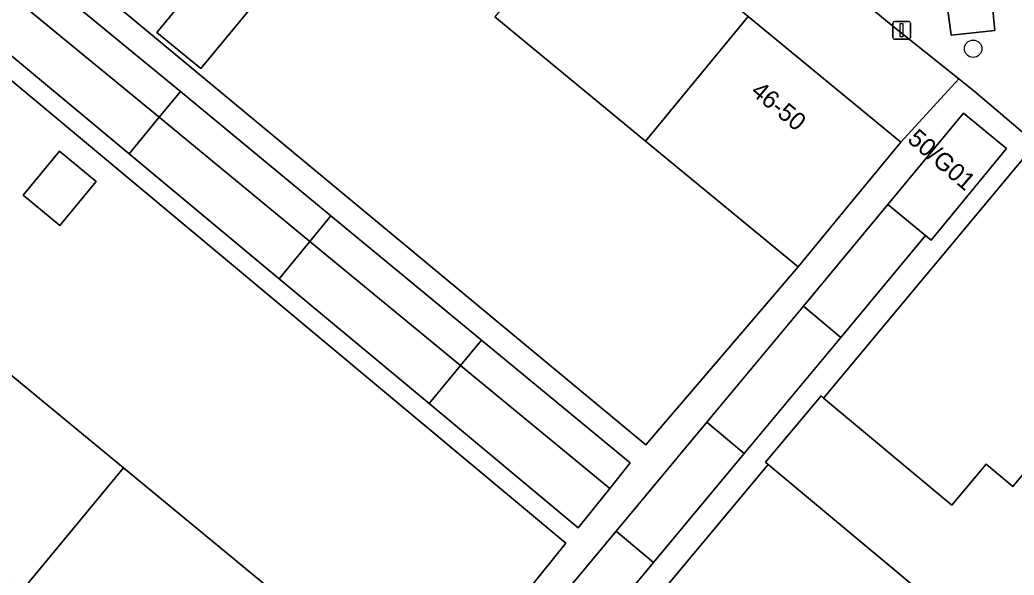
# Model space of a CAD drawing. Extents: x 162073 to 163043, y 381818 to 382561.
# Drawn here: x 162389.4 to 162445.3, y 382038.3 to 382069.6 of the extents above; entities that cross this region are included whole.
import ezdxf

# ---------------------------------------------------------------- set-up
doc = ezdxf.new("R2010")
doc.units = 0
for name, color, linetype in [('IMGEO_Boom', 7, 'Continuous'), ('IMGEO_Erf', 7, 'Continuous'), ('IMGEO_Lichtmast', 7, 'Continuous'), ('IMGEO_Pand', 7, 'Continuous'), ('IMGEO_Pand_nummerreeks', 7, 'Continuous'), ('IMGEO_Parkeervlak_open', 7, 'Continuous'), ('IMGEO_Voetpad_open', 7, 'Continuous')]:
    doc.layers.add(name, color=color, linetype=linetype)

msp = doc.modelspace()

# ---------------------------------------------------------------- linework, layer by layer
at = {"layer": 'IMGEO_Boom'}
msp.add_circle((162443, 382067.946), 0.489, dxfattribs=at)
at = {"layer": 'IMGEO_Erf'}
for points in [[(162374.058, 382122.534), (162370.927, 382118.714), (162379.513, 382111.639), (162387.985, 382104.658), (162396.457, 382097.677), (162404.928, 382090.697), (162413.399, 382083.717), (162421.871, 382076.736), (162430.342, 382069.755), (162438.929, 382062.68), (162442.197, 382066.248), (162438.394, 382069.293)], [(162352.681, 382096.404), (162344.316, 382086.382), (162352.799, 382079.379), (162361.282, 382072.376), (162369.765, 382065.374), (162378.248, 382058.371), (162386.731, 382051.368), (162395.214, 382044.365), (162403.697, 382037.363), (162412.215, 382030.331), (162420.1, 382040.13)], [(162393.681, 382060.479), (162391.639, 382058.007), (162389.571, 382059.714), (162391.612, 382062.187)]]:
    msp.add_lwpolyline(points, close=True, dxfattribs=at)
for points in [[(162367.87, 382092.748), (162424.591, 382045.656), (162433.159, 382055.677), (162424.572, 382062.752), (162416.1, 382069.733)], [(162406.221, 382074.898), (162399.57, 382066.827), (162397.097, 382068.865), (162398.824, 382070.962)], [(162454.536, 382056.174), (162446.525, 382062.616), (162434.583, 382048.291), (162441.797, 382042.258), (162443.737, 382044.571), (162445.238, 382043.312), (162447.3, 382045.77), (162449.243, 382048.087), (162447.533, 382049.521), (162450.592, 382053.167), (162452.277, 382051.753), (162454.432, 382054.322)], [(162430.078, 382030.919), (162432.415, 382033.705), (162433.745, 382032.589), (162436.679, 382036.087), (162438.155, 382034.848), (162440.187, 382037.271), (162431.473, 382044.558), (162411.121, 382020.146)]]:
    msp.add_lwpolyline(points, dxfattribs=at)
at = {"layer": 'IMGEO_Lichtmast'}
for p, q in [((162438.48, 382068.581), (162438.48, 382069.381)), ((162438.48, 382069.381), (162438.48, 382068.581)), ((162438.58, 382069.481), (162439.37, 382069.481)), ((162439.37, 382069.481), (162438.58, 382069.481)), ((162439.47, 382069.381), (162439.47, 382068.581)), ((162439.47, 382068.581), (162439.47, 382069.381)), ((162439.37, 382068.481), (162438.58, 382068.481)), ((162438.58, 382068.481), (162439.37, 382068.481))]:
    msp.add_line(p, q, dxfattribs=at)
msp.add_lwpolyline([(162438.9, 382069.356), (162439.05, 382069.356), (162439.05, 382068.606), (162438.9, 382068.606), (162438.9, 382069.356)], dxfattribs=at)
for centre, start, end in [((162438.58, 382069.381), 90, 180), ((162438.58, 382069.381), 90, 180), ((162439.37, 382069.381), 0, 90), ((162439.37, 382069.381), 360, 90), ((162438.58, 382068.581), 180, 270), ((162438.58, 382068.581), 180, 270), ((162439.37, 382068.581), 270, 0), ((162439.37, 382068.581), 270, 0)]:
    msp.add_arc(centre, 0.1, start, end, dxfattribs=at)
at = {"layer": 'IMGEO_Pand'}
for points in [[(162404.928, 382090.697), (162399.157, 382083.694), (162397.197, 382081.316), (162401.766, 382077.552), (162397.342, 382072.183), (162398.824, 382070.962), (162397.097, 382068.865), (162399.57, 382066.827), (162406.221, 382074.898), (162405.257, 382075.693), (162406.717, 382077.465), (162407.629, 382076.713), (162413.399, 382083.717)], [(162424.572, 382062.752), (162430.342, 382069.755), (162421.871, 382076.736), (162416.1, 382069.733)], [(162389.955, 382072.525), (162388.753, 382071.067), (162397.225, 382064.085), (162398.418, 382065.534)], [(162395.528, 382062.026), (162397.225, 382064.085), (162388.753, 382071.067), (162387.093, 382069.052)], [(162424.572, 382062.752), (162433.159, 382055.677), (162435.75, 382058.822), (162438.929, 382062.68), (162430.342, 382069.755)], [(162397.225, 382064.085), (162405.695, 382057.105), (162406.881, 382058.544), (162398.418, 382065.534)], [(162444.879, 382062.326), (162442.45, 382064.327), (162438.206, 382059.176), (162440.325, 382057.43), (162440.635, 382057.175)], [(162395.528, 382062.026), (162403.962, 382055.001), (162405.695, 382057.105), (162397.225, 382064.085)], [(162393.681, 382060.479), (162391.612, 382062.187), (162389.571, 382059.714), (162391.639, 382058.007)], [(162440.325, 382057.43), (162438.206, 382059.176), (162433.451, 382053.462), (162435.561, 382051.705)], [(162406.881, 382058.544), (162405.695, 382057.105), (162414.167, 382050.123), (162415.345, 382051.553)], [(162412.397, 382047.975), (162414.167, 382050.123), (162405.695, 382057.105), (162403.962, 382055.001)], [(162433.451, 382053.462), (162428.013, 382046.927), (162430.124, 382045.17), (162435.561, 382051.705)], [(162381.001, 382044.426), (162389.484, 382037.423), (162395.214, 382044.365), (162386.731, 382051.368)], [(162414.167, 382050.123), (162422.567, 382043.201), (162423.719, 382044.636), (162415.345, 382051.553)], [(162412.397, 382047.975), (162420.788, 382040.985), (162422.567, 382043.201), (162414.167, 382050.123)], [(162447.3, 382045.77), (162445.238, 382043.312), (162443.737, 382044.571), (162441.797, 382042.258), (162434.583, 382048.291), (162434.446, 382048.406), (162431.329, 382044.679), (162431.473, 382044.558), (162440.187, 382037.271), (162446.937, 382031.626), (162447.733, 382032.574), (162448.308, 382032.092), (162449.816, 382033.89), (162449.21, 382034.398), (162451.7, 382037.366), (162452.284, 382036.876), (162453.838, 382038.728), (162453.287, 382039.19), (162454.063, 382040.114)], [(162430.124, 382045.17), (162428.013, 382046.927), (162422.917, 382040.802), (162425.028, 382039.045)], [(162403.697, 382037.363), (162395.214, 382044.365), (162389.484, 382037.423), (162397.967, 382030.421)], [(162425.028, 382039.045), (162422.917, 382040.802), (162417.517, 382034.312), (162419.629, 382032.555)]]:
    msp.add_lwpolyline(points, close=True, dxfattribs=at)
at = {"layer": 'IMGEO_Parkeervlak_open'}
msp.add_lwpolyline([(162441.451, 382071.1), (162441.755, 382068.708), (162444.221, 382068.98), (162443.882, 382072.46)], dxfattribs=at)
at = {"layer": 'IMGEO_Voetpad_open'}
for points in [[(162356.934, 382136.569), (162372.628, 382123.707), (162374.058, 382122.534), (162438.394, 382069.293), (162442.197, 382066.248), (162443.042, 382065.571), (162446.525, 382062.616), (162454.536, 382056.174)], [(162352.681, 382096.404), (162420.1, 382040.13), (162412.215, 382030.331)], [(162411.121, 382020.146), (162431.473, 382044.558), (162431.329, 382044.679), (162434.446, 382048.406), (162434.583, 382048.291), (162446.525, 382062.616), (162443.042, 382065.571), (162442.197, 382066.248), (162438.929, 382062.68), (162435.75, 382058.822), (162433.159, 382055.677), (162424.591, 382045.656), (162367.87, 382092.748)], [(162449.709, 382064.013), (162447.637, 382065.739), (162445.4, 382071.193), (162443.882, 382072.46), (162444.221, 382068.98), (162441.755, 382068.708), (162441.451, 382071.1), (162438.969, 382070.857), (162438.688, 382073.348)], [(162417.517, 382034.312), (162422.917, 382040.802), (162428.013, 382046.927), (162433.451, 382053.462), (162438.206, 382059.176), (162442.45, 382064.327), (162444.879, 382062.326), (162440.635, 382057.175), (162440.325, 382057.43), (162435.561, 382051.705), (162430.124, 382045.17), (162425.028, 382039.045), (162419.629, 382032.555)]]:
    msp.add_lwpolyline(points, dxfattribs=at)
msp.add_lwpolyline([(162423.719, 382044.636), (162422.567, 382043.201), (162420.788, 382040.985), (162412.397, 382047.975), (162403.962, 382055.001), (162395.528, 382062.026), (162387.093, 382069.052), (162378.659, 382076.078), (162370.225, 382083.104), (162361.791, 382090.129), (162353.327, 382097.179), (162354.842, 382099.014), (162356.077, 382100.509), (162364.566, 382093.497), (162373.029, 382086.507), (162381.492, 382079.516), (162389.955, 382072.525), (162398.418, 382065.534), (162406.881, 382058.544), (162415.345, 382051.553)], close=True, dxfattribs=at)

# ---------------------------------------------------------------- texts
at = {"layer": 'IMGEO_Pand_nummerreeks'}
for s, rotation, p in [('46-50', 320.5113, (162430.433, 382065.43)), ('50/G01', 319.1825, (162439.248, 382062.76))]:
    msp.add_text(s, height=1, rotation=rotation, dxfattribs=at).set_placement(p)

doc.saveas('drawing.dxf')
